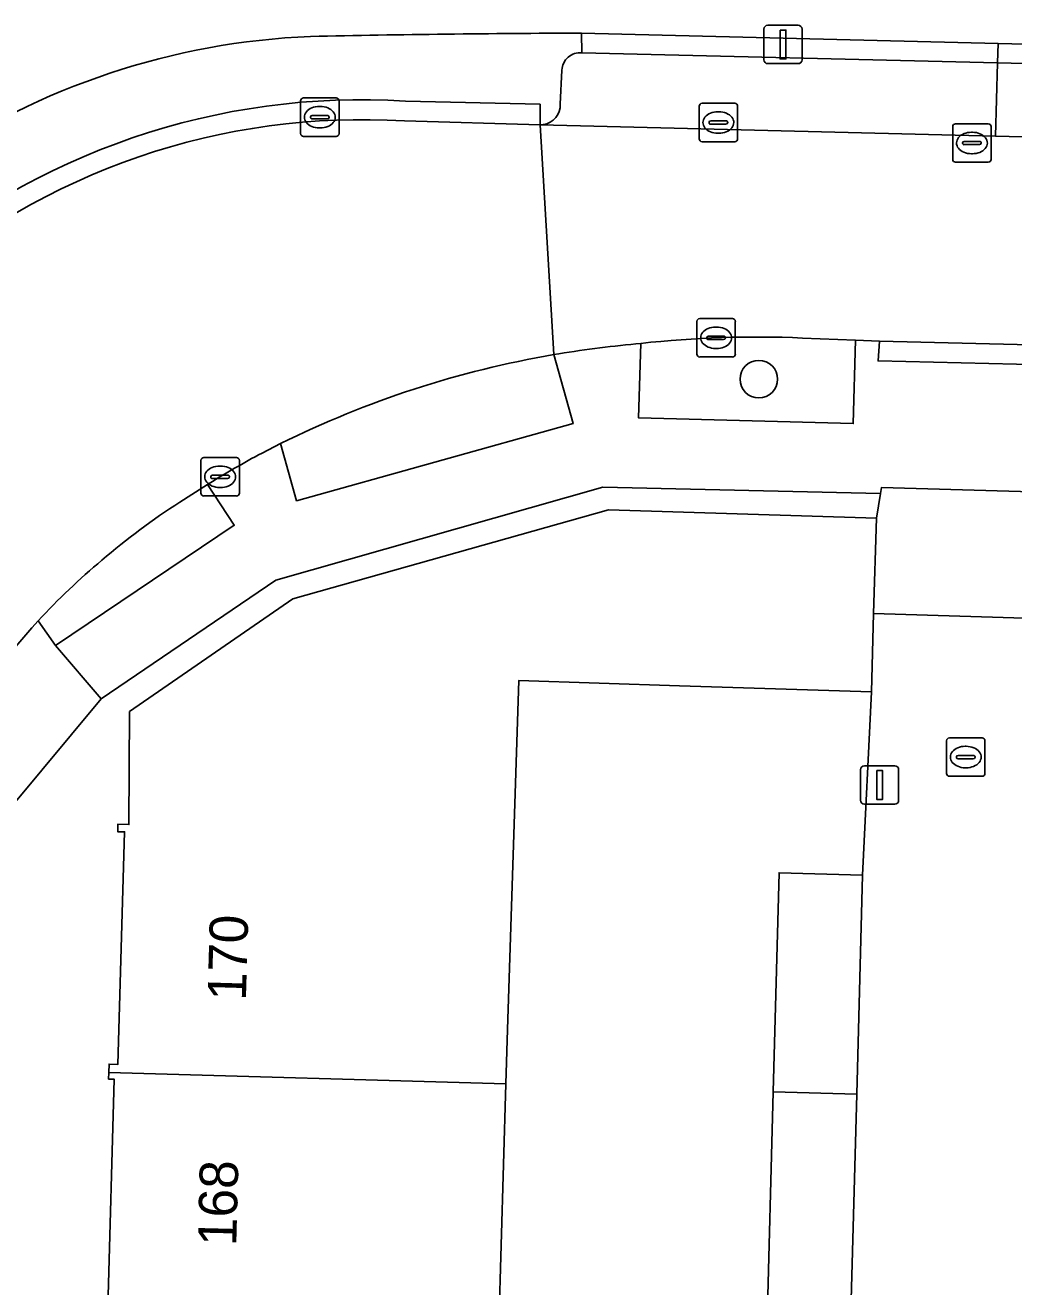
# Model space of a CAD drawing. Extents: x 162082 to 163401, y 388089 to 388636.
# Drawn here: x 162343.72 to 162369.45, y 388439.93 to 388472.76 of the extents above; entities that cross this region are included whole.
import ezdxf

# ---------------------------------------------------------------- set-up
doc = ezdxf.new("R2010")
doc.units = 0
for name, color, linetype in [('IMGEO_Berm_open', 7, 'Continuous'), ('IMGEO_Boom', 7, 'Continuous'), ('IMGEO_Erf', 7, 'Continuous'), ('IMGEO_Fietspad_gesloten', 7, 'Continuous'), ('IMGEO_Groenvoorziening', 7, 'Continuous'), ('IMGEO_Kolk', 7, 'Continuous'), ('IMGEO_Lichtmast', 7, 'Continuous'), ('IMGEO_Pand', 7, 'Continuous'), ('IMGEO_Pand_nummerreeks', 7, 'Continuous'), ('IMGEO_Parkeervlak_open', 7, 'Continuous'), ('IMGEO_Rijbaan_lokaal_gesloten', 7, 'Continuous'), ('IMGEO_Rijbaan_lokaal_open', 7, 'Continuous'), ('IMGEO_Rioolput', 7, 'Continuous'), ('IMGEO_Voetpad_open', 7, 'Continuous')]:
    doc.layers.add(name, color=color, linetype=linetype)

msp = doc.modelspace()

# ---------------------------------------------------------------- linework, layer by layer
at = {"layer": 'IMGEO_Berm_open'}
msp.add_lwpolyline([(162358.201, 388472.554), (162358.203, 388472.042), (162369.02, 388471.78), (162369.037, 388472.285)], close=True, dxfattribs=at)
at = {"layer": 'IMGEO_Boom'}
msp.add_circle((162362.811, 388463.549), 0.489, dxfattribs=at)
at = {"layer": 'IMGEO_Erf'}
for points in [[(162345.868, 388439.383), (162346.041, 388445.333), (162345.892, 388445.338), (162345.897, 388445.509), (162345.903, 388445.725), (162346.134, 388445.718), (162346.31, 388451.772), (162346.13, 388451.772), (162346.132, 388451.968), (162346.42, 388451.96), (162346.44, 388454.9), (162350.69, 388457.83), (162358.9, 388460.15), (162365.87, 388459.93), (162365.975, 388460.578), (162358.756, 388460.74), (162350.246, 388458.32), (162345.699, 388455.235), (162343.386, 388452.443), (162341.671, 388388.741)], [(162362.018, 388400.921), (162362.185, 388407.22), (162362.352, 388413.517), (162362.449, 388417.176), (162362.519, 388419.817), (162362.686, 388426.113), (162362.853, 388432.41), (162363.02, 388438.709), (162363.187, 388445.007), (162363.338, 388450.704), (162365.51, 388450.646), (162365.74, 388455.41), (162360.743, 388455.573), (162356.57, 388455.71), (162356.269, 388446.627), (162356.228, 388445.209), (162356.044, 388438.912), (162355.86, 388432.614), (162355.677, 388426.317), (162355.493, 388420.021), (162355.31, 388413.722), (162355.126, 388407.425), (162354.942, 388401.127), (162354.759, 388394.83)]]:
    msp.add_lwpolyline(points, dxfattribs=at)
at = {"layer": 'IMGEO_Fietspad_gesloten'}
msp.add_lwpolyline([(162358.201, 388472.554), (162369.037, 388472.285), (162375.078, 388472.135), (162386.708, 388471.847), (162390.238, 388471.759), (162401.837, 388471.472), (162408.03, 388471.318), (162408.007, 388470.829), (162416.505, 388470.602), (162416.525, 388471.113), (162420.862, 388471.019), (162440.416, 388470.49), (162440.436, 388470.49), (162448.448, 388470.301), (162458.442, 388470.036), (162464.998, 388469.844), (162475.747, 388469.573), (162481.767, 388469.41), (162492.263, 388469.129), (162498.783, 388468.948), (162509.296, 388468.657)], dxfattribs=at)
for centre, radius, start, end in [((162351.969, 388453.321), 19.166, 92.4584, 124.2977), ((162359.637, 388055.756), 416.8, 90.19737, 91.16714)]:
    msp.add_arc(centre, radius, start, end, dxfattribs=at)
at = {"layer": 'IMGEO_Groenvoorziening'}
for points in [[(162359.741, 388464.48), (162359.684, 388462.54), (162365.27, 388462.394), (162365.328, 388464.563)], [(162365.328, 388464.563), (162363.947, 388464.619)], [(162350.369, 388461.874), (162350.783, 388460.383), (162357.982, 388462.393), (162357.479, 388464.187)], [(162349.16, 388459.748), (162348.465, 388460.809), (162347.745, 388460.351)], [(162344.06, 388457.261), (162344.51, 388456.617), (162349.16, 388459.748)]]:
    msp.add_lwpolyline(points, dxfattribs=at)
for centre, radius, start, end in [((162362.739, 388437.47), 27.176, 87.4521, 96.3336), ((162361.826, 388438.741), 25.814, 99.6938, 116.3473), ((162357.594, 388445.058), 18.19, 122.7813, 130.75), ((162357.048, 388445.251), 17.69, 129.8206, 137.2418)]:
    msp.add_arc(centre, radius, start, end, dxfattribs=at)
at = {"layer": 'IMGEO_Kolk'}
for p, q in [((162361.333, 388470.727), (162362.185, 388470.727)), ((162361.258, 388469.801), (162361.258, 388470.653)), ((162361.746, 388470.507), (162361.771, 388470.507)), ((162362.259, 388470.653), (162362.259, 388469.801)), ((162361.517, 388470.221), (162361.517, 388470.233)), ((162361.955, 388470.184), (162361.557, 388470.184)), ((162361.56, 388470.27), (162361.958, 388470.27)), ((162362.001, 388470.233), (162362.001, 388470.221)), ((162361.769, 388469.947), (162361.744, 388469.947)), ((162362.185, 388469.727), (162361.333, 388469.727)), ((162361.199, 388464.2), (162361.199, 388465.052)), ((162361.274, 388465.126), (162362.126, 388465.126)), ((162361.687, 388464.906), (162361.712, 388464.906)), ((162362.2, 388465.052), (162362.2, 388464.2)), ((162361.458, 388464.62), (162361.458, 388464.632)), ((162361.896, 388464.583), (162361.498, 388464.583)), ((162361.501, 388464.669), (162361.899, 388464.669)), ((162361.942, 388464.632), (162361.942, 388464.62)), ((162361.71, 388464.346), (162361.685, 388464.346)), ((162362.126, 388464.126), (162361.274, 388464.126)), ((162348.294, 388460.583), (162348.294, 388461.435)), ((162348.369, 388461.509), (162349.221, 388461.509)), ((162348.782, 388461.289), (162348.807, 388461.289)), ((162349.295, 388461.435), (162349.295, 388460.583)), ((162348.553, 388461.003), (162348.553, 388461.015)), ((162348.991, 388460.966), (162348.593, 388460.966)), ((162348.596, 388461.052), (162348.994, 388461.052)), ((162349.037, 388461.015), (162349.037, 388461.003)), ((162348.805, 388460.729), (162348.78, 388460.729)), ((162349.221, 388460.509), (162348.369, 388460.509)), ((162367.695, 388453.29), (162367.695, 388454.142)), ((162367.77, 388454.216), (162368.622, 388454.216)), ((162368.183, 388453.996), (162368.208, 388453.996)), ((162368.696, 388454.142), (162368.696, 388453.29)), ((162367.954, 388453.71), (162367.954, 388453.722)), ((162368.392, 388453.673), (162367.994, 388453.673)), ((162367.997, 388453.759), (162368.395, 388453.759)), ((162368.438, 388453.722), (162368.438, 388453.71)), ((162368.206, 388453.436), (162368.181, 388453.436)), ((162368.622, 388453.216), (162367.77, 388453.216))]:
    msp.add_line(p, q, dxfattribs=at)
for points in [[(162361.333, 388470.727), (162362.185, 388470.727)], [(162361.258, 388469.801), (162361.258, 388470.653)], [(162362.259, 388470.653), (162362.259, 388469.801)], [(162362.185, 388469.727), (162361.333, 388469.727)], [(162361.199, 388464.2), (162361.199, 388465.052)], [(162361.274, 388465.126), (162362.126, 388465.126)], [(162362.2, 388465.052), (162362.2, 388464.2)], [(162362.126, 388464.126), (162361.274, 388464.126)], [(162348.294, 388460.583), (162348.294, 388461.435)], [(162348.369, 388461.509), (162349.221, 388461.509)], [(162349.295, 388461.435), (162349.295, 388460.583)], [(162349.221, 388460.509), (162348.369, 388460.509)], [(162367.695, 388453.29), (162367.695, 388454.142)], [(162367.77, 388454.216), (162368.622, 388454.216)], [(162368.696, 388454.142), (162368.696, 388453.29)], [(162368.622, 388453.216), (162367.77, 388453.216)]]:
    msp.add_lwpolyline(points, dxfattribs=at)
for centre, radius, start, end in [((162361.335, 388470.651), 0.0765, 91.552, 178.448), ((162361.335, 388470.651), 0.0765, 91.552, 178.448), ((162362.183, 388470.651), 0.0765, 1.552, 88.448), ((162362.183, 388470.651), 0.0765, 1.552, 88.448), ((162361.557, 388470.23), 0.0403, 85.8775, 175.7526), ((162361.554, 388470.22), 0.0366, 178.938, 274.7102), ((162361.958, 388470.227), 0.043, 264.8664, 352.4533), ((162361.962, 388470.232), 0.0386, 1.7309, 96.639), ((162361.335, 388469.803), 0.0765, 181.552, 268.448), ((162361.335, 388469.803), 0.0765, 181.552, 268.448), ((162362.183, 388469.803), 0.0765, 271.552, 358.448), ((162362.183, 388469.803), 0.0765, 271.552, 358.448), ((162361.276, 388465.05), 0.0765, 91.552, 178.448), ((162361.276, 388465.05), 0.0765, 91.552, 178.448), ((162362.124, 388465.05), 0.0765, 1.552, 88.448), ((162362.124, 388465.05), 0.0765, 1.552, 88.448), ((162361.498, 388464.629), 0.0403, 85.8775, 175.7526), ((162361.495, 388464.619), 0.0366, 178.938, 274.7102), ((162361.899, 388464.626), 0.043, 264.8664, 352.4533), ((162361.903, 388464.631), 0.0386, 1.7309, 96.639), ((162361.276, 388464.202), 0.0765, 181.552, 268.448), ((162361.276, 388464.202), 0.0765, 181.552, 268.448), ((162362.124, 388464.202), 0.0765, 271.552, 358.448), ((162362.124, 388464.202), 0.0765, 271.552, 358.448), ((162348.371, 388461.433), 0.0765, 91.552, 178.448), ((162348.371, 388461.433), 0.0765, 91.552, 178.448), ((162349.219, 388461.433), 0.0765, 1.552, 88.448), ((162349.219, 388461.433), 0.0765, 1.552, 88.448), ((162348.593, 388461.012), 0.0403, 85.8775, 175.7526), ((162348.59, 388461.002), 0.0366, 178.938, 274.7102), ((162348.994, 388461.009), 0.043, 264.8664, 352.4533), ((162348.998, 388461.014), 0.0386, 1.7309, 96.639), ((162348.371, 388460.585), 0.0765, 181.552, 268.448), ((162348.371, 388460.585), 0.0765, 181.552, 268.448), ((162349.219, 388460.585), 0.0765, 271.552, 358.448), ((162349.219, 388460.585), 0.0765, 271.552, 358.448), ((162367.772, 388454.14), 0.0765, 91.552, 178.448), ((162367.772, 388454.14), 0.0765, 91.552, 178.448), ((162368.62, 388454.14), 0.0765, 1.552, 88.448), ((162368.62, 388454.14), 0.0765, 1.552, 88.448), ((162367.994, 388453.719), 0.0403, 85.8775, 175.7526), ((162367.991, 388453.709), 0.0366, 178.938, 274.7102), ((162368.395, 388453.716), 0.043, 264.8664, 352.4533), ((162368.399, 388453.721), 0.0386, 1.7309, 96.639), ((162367.772, 388453.292), 0.0765, 181.552, 268.448), ((162367.772, 388453.292), 0.0765, 181.552, 268.448), ((162368.62, 388453.292), 0.0765, 271.552, 358.448), ((162368.62, 388453.292), 0.0765, 271.552, 358.448)]:
    msp.add_arc(centre, radius, start, end, dxfattribs=at)
for centre, major_axis, ratio, start_param, end_param in [((162361.745, 388470.227), (-0.387, 0.002), 0.722429, 4.712389, 7.853982), ((162361.77, 388470.227), (-0.39, 0.002), 0.717154, 1.570796, 4.712389), ((162361.686, 388464.626), (-0.387, 0.002), 0.722429, 4.712389, 7.853982), ((162361.711, 388464.626), (-0.39, 0.002), 0.717154, 1.570796, 4.712389), ((162348.781, 388461.009), (-0.387, 0.002), 0.722429, 4.712389, 7.853982), ((162348.806, 388461.009), (-0.39, 0.002), 0.717154, 1.570796, 4.712389), ((162368.182, 388453.716), (-0.387, 0.002), 0.722429, 4.712389, 7.853982), ((162368.207, 388453.716), (-0.39, 0.002), 0.717154, 1.570796, 4.712389)]:
    msp.add_ellipse(centre, major_axis=major_axis, ratio=ratio, start_param=start_param, end_param=end_param, dxfattribs=at)
at = {"layer": 'IMGEO_Lichtmast'}
for p, q in [((162363.045, 388472.759), (162363.835, 388472.759)), ((162363.835, 388472.759), (162363.045, 388472.759)), ((162362.945, 388471.859), (162362.945, 388472.659)), ((162362.945, 388472.659), (162362.945, 388471.859)), ((162363.935, 388472.659), (162363.935, 388471.859)), ((162363.935, 388471.859), (162363.935, 388472.659)), ((162363.835, 388471.759), (162363.045, 388471.759)), ((162363.045, 388471.759), (162363.835, 388471.759)), ((162365.46, 388452.59), (162365.46, 388453.39)), ((162365.46, 388453.39), (162365.46, 388452.59)), ((162365.56, 388453.49), (162366.35, 388453.49)), ((162366.35, 388453.49), (162365.56, 388453.49)), ((162366.45, 388453.39), (162366.45, 388452.59)), ((162366.45, 388452.59), (162366.45, 388453.39)), ((162366.35, 388452.49), (162365.56, 388452.49)), ((162365.56, 388452.49), (162366.35, 388452.49))]:
    msp.add_line(p, q, dxfattribs=at)
for points in [[(162363.365, 388472.634), (162363.515, 388472.634), (162363.515, 388471.884), (162363.365, 388471.884), (162363.365, 388472.634)], [(162365.88, 388453.365), (162366.03, 388453.365), (162366.03, 388452.615), (162365.88, 388452.615), (162365.88, 388453.365)]]:
    msp.add_lwpolyline(points, dxfattribs=at)
for centre, start, end in [((162363.045, 388472.659), 90, 180), ((162363.045, 388472.659), 90, 180), ((162363.835, 388472.659), 0, 90), ((162363.835, 388472.659), 360, 90), ((162363.045, 388471.859), 180, 270), ((162363.045, 388471.859), 180, 270), ((162363.835, 388471.859), 270, 0), ((162363.835, 388471.859), 270, 0), ((162365.56, 388453.39), 90, 180), ((162365.56, 388453.39), 90, 180), ((162366.35, 388453.39), 0, 90), ((162366.35, 388453.39), 360, 90), ((162365.56, 388452.59), 180, 270), ((162365.56, 388452.59), 180, 270), ((162366.35, 388452.59), 270, 0), ((162366.35, 388452.59), 270, 0)]:
    msp.add_arc(centre, 0.1, start, end, dxfattribs=at)
at = {"layer": 'IMGEO_Pand'}
for points in [[(162345.897, 388445.509), (162356.228, 388445.209), (162356.269, 388446.627), (162356.57, 388455.71), (162360.743, 388455.573), (162365.74, 388455.41), (162365.799, 388457.454), (162365.87, 388459.93), (162358.9, 388460.15), (162350.69, 388457.83), (162346.44, 388454.9), (162346.42, 388451.96), (162346.132, 388451.968), (162346.13, 388451.772), (162346.31, 388451.772), (162346.134, 388445.718), (162345.903, 388445.725)], [(162365.51, 388450.646), (162363.338, 388450.704), (162363.187, 388445.007), (162365.359, 388444.944)], [(162345.897, 388445.509), (162345.892, 388445.338), (162346.041, 388445.333), (162345.868, 388439.383), (162345.726, 388439.387), (162345.721, 388439.212), (162356.044, 388438.912), (162356.228, 388445.209)], [(162363.02, 388438.709), (162365.192, 388438.646), (162365.359, 388444.944), (162363.187, 388445.007)]]:
    msp.add_lwpolyline(points, close=True, dxfattribs=at)
at = {"layer": 'IMGEO_Parkeervlak_open'}
for points in [[(162369.02, 388471.78), (162358.203, 388472.042)], [(162357.2, 388470.174), (162357.12, 388470.167), (162368.972, 388469.873), (162369.02, 388471.78)], [(162357.689, 388471.589), (162357.643, 388470.708)]]:
    msp.add_lwpolyline(points, dxfattribs=at)
for centre, radius, start, end in [((162358.159, 388471.574), 0.47, 84.6243, 178.1566), ((162357.134, 388470.68), 0.51, 277.466, 3.1766)]:
    msp.add_arc(centre, radius, start, end, dxfattribs=at)
at = {"layer": 'IMGEO_Rijbaan_lokaal_gesloten'}
for points in [[(162357.479, 388464.187), (162357.12, 388470.167), (162353.588, 388470.267)], [(162504.674, 388466.396), (162498.717, 388466.552), (162492.196, 388466.723), (162481.721, 388466.997), (162474.776, 388467.179), (162471.449, 388467.262), (162471.402, 388467.266), (162464.938, 388467.441), (162458.384, 388467.618), (162448.429, 388467.886), (162439.373, 388468.131), (162439.33, 388468.131), (162438.401, 388468.167), (162419.774, 388468.618), (162418.749, 388468.644), (162408.223, 388468.89), (162403.702, 388469.023), (162402.728, 388469.034), (162390.18, 388469.346), (162386.66, 388469.431), (162375.01, 388469.723), (162368.972, 388469.873), (162357.12, 388470.167), (162357.479, 388464.187)], [(162359.611, 388464.465), (162359.741, 388464.48)], [(162363.947, 388464.619), (162365.328, 388464.563), (162365.948, 388464.538), (162370.967, 388464.412), (162371.659, 388464.386), (162390.127, 388463.916), (162391.354, 388463.895), (162408.184, 388463.445), (162420.621, 388463.13), (162421.807, 388463.11), (162462.126, 388462.081), (162463.206, 388462.062), (162475.436, 388461.725), (162497.037, 388461.139)], [(162349.884, 388461.627), (162350.369, 388461.874)], [(162347.745, 388460.351), (162348.465, 388460.809)]]:
    msp.add_lwpolyline(points, dxfattribs=at)
for centre, radius, start, end in [((162352.479, 388452.437), 17.865, 86.4419, 131.4689), ((162362.739, 388437.47), 27.176, 87.4521, 96.3336), ((162361.826, 388438.741), 25.814, 99.6938, 116.3473), ((162362.141, 388436.748), 27.832, 95.2155, 99.6428), ((162363.427, 388436.495), 28.549, 118.318, 121.6056), ((162357.594, 388445.058), 18.19, 122.7813, 130.75), ((162357.048, 388445.251), 17.69, 129.8206, 137.2418), ((162356.489, 388445.794), 16.911, 137.3069, 163.4762)]:
    msp.add_arc(centre, radius, start, end, dxfattribs=at)
at = {"layer": 'IMGEO_Rijbaan_lokaal_open'}
msp.add_lwpolyline([(162370.644, 388460.18), (162370.536, 388460.18), (162370.521, 388460.602), (162366.001, 388460.726), (162365.975, 388460.578), (162365.87, 388459.93), (162365.799, 388457.454), (162370.574, 388457.3)], close=True, dxfattribs=at)
msp.add_lwpolyline([(162370.574, 388457.3), (162365.799, 388457.454), (162365.74, 388455.41), (162365.51, 388450.646), (162365.359, 388444.944), (162365.192, 388438.646), (162365.025, 388432.347), (162364.858, 388426.05), (162364.754, 388422.116), (162366.299, 388422.059), (162369.325, 388421.97), (162372.351, 388421.882)], dxfattribs=at)
at = {"layer": 'IMGEO_Rioolput'}
for p, q in [((162350.888, 388469.939), (162350.888, 388470.791)), ((162350.963, 388470.865), (162351.815, 388470.865)), ((162351.889, 388470.791), (162351.889, 388469.939)), ((162351.19, 388470.408), (162351.588, 388470.408)), ((162351.376, 388470.645), (162351.401, 388470.645)), ((162351.147, 388470.359), (162351.147, 388470.371)), ((162351.585, 388470.322), (162351.187, 388470.322)), ((162351.399, 388470.085), (162351.374, 388470.085)), ((162351.631, 388470.371), (162351.631, 388470.359)), ((162367.856, 388469.268), (162367.856, 388470.12)), ((162367.931, 388470.194), (162368.783, 388470.194)), ((162368.857, 388470.12), (162368.857, 388469.268)), ((162351.815, 388469.865), (162350.963, 388469.865)), ((162368.158, 388469.737), (162368.556, 388469.737)), ((162368.344, 388469.974), (162368.369, 388469.974)), ((162368.115, 388469.688), (162368.115, 388469.7)), ((162368.553, 388469.651), (162368.155, 388469.651)), ((162368.367, 388469.414), (162368.342, 388469.414)), ((162368.599, 388469.7), (162368.599, 388469.688)), ((162368.783, 388469.194), (162367.931, 388469.194))]:
    msp.add_line(p, q, dxfattribs=at)
for points in [[(162350.888, 388469.939), (162350.888, 388470.791)], [(162350.963, 388470.865), (162351.815, 388470.865)], [(162351.889, 388470.791), (162351.889, 388469.939)], [(162367.856, 388469.268), (162367.856, 388470.12)], [(162367.931, 388470.194), (162368.783, 388470.194)], [(162368.857, 388470.12), (162368.857, 388469.268)], [(162351.815, 388469.865), (162350.963, 388469.865)], [(162368.783, 388469.194), (162367.931, 388469.194)]]:
    msp.add_lwpolyline(points, dxfattribs=at)
for centre, radius, start, end in [((162350.965, 388470.789), 0.0765, 91.552, 178.448), ((162350.965, 388470.789), 0.0765, 91.552, 178.448), ((162351.813, 388470.789), 0.0765, 1.552, 88.448), ((162351.813, 388470.789), 0.0765, 1.552, 88.448), ((162351.187, 388470.368), 0.0403, 85.8775, 175.7526), ((162351.592, 388470.37), 0.0386, 1.7309, 96.639), ((162351.184, 388470.358), 0.0366, 178.938, 274.7102), ((162351.588, 388470.365), 0.043, 264.8664, 352.4533), ((162367.933, 388470.118), 0.0765, 91.552, 178.448), ((162367.933, 388470.118), 0.0765, 91.552, 178.448), ((162368.781, 388470.118), 0.0765, 1.552, 88.448), ((162368.781, 388470.118), 0.0765, 1.552, 88.448), ((162350.965, 388469.941), 0.0765, 181.552, 268.448), ((162350.965, 388469.941), 0.0765, 181.552, 268.448), ((162351.813, 388469.941), 0.0765, 271.552, 358.448), ((162351.813, 388469.941), 0.0765, 271.552, 358.448), ((162368.155, 388469.697), 0.0403, 85.8775, 175.7526), ((162368.56, 388469.699), 0.0386, 1.7309, 96.639), ((162368.152, 388469.687), 0.0366, 178.938, 274.7102), ((162368.556, 388469.694), 0.043, 264.8664, 352.4533), ((162367.933, 388469.27), 0.0765, 181.552, 268.448), ((162367.933, 388469.27), 0.0765, 181.552, 268.448), ((162368.781, 388469.27), 0.0765, 271.552, 358.448), ((162368.781, 388469.27), 0.0765, 271.552, 358.448)]:
    msp.add_arc(centre, radius, start, end, dxfattribs=at)
for centre, major_axis, ratio, start_param, end_param in [((162351.375, 388470.365), (-0.387, 0.002), 0.722429, 4.712389, 7.853982), ((162351.4, 388470.365), (-0.39, 0.002), 0.717154, 1.570796, 4.712389), ((162368.343, 388469.694), (-0.387, 0.002), 0.722429, 4.712389, 7.853982), ((162368.368, 388469.694), (-0.39, 0.002), 0.717154, 1.570796, 4.712389)]:
    msp.add_ellipse(centre, major_axis=major_axis, ratio=ratio, start_param=start_param, end_param=end_param, dxfattribs=at)
at = {"layer": 'IMGEO_Voetpad_open'}
for points in [[(162358.203, 388472.042), (162358.201, 388472.554)], [(162357.643, 388470.708), (162357.689, 388471.589)], [(162353.588, 388470.267), (162357.12, 388470.167), (162357.12, 388470.702), (162353.614, 388470.786)], [(162353.614, 388470.786), (162357.12, 388470.702), (162357.12, 388470.167)], [(162357.12, 388470.167), (162357.2, 388470.174)], [(162371.659, 388464.386), (162370.967, 388464.412), (162370.954, 388463.902), (162365.916, 388464.025), (162365.948, 388464.538), (162365.328, 388464.563), (162365.27, 388462.394), (162359.684, 388462.54), (162359.741, 388464.48), (162359.611, 388464.465)], [(162357.479, 388464.187), (162357.982, 388462.393), (162350.783, 388460.383), (162350.369, 388461.874), (162349.884, 388461.627)], [(162348.465, 388460.809), (162349.16, 388459.748), (162344.51, 388456.617), (162345.699, 388455.235), (162350.246, 388458.32), (162358.756, 388460.74), (162365.975, 388460.578), (162366.001, 388460.726), (162370.521, 388460.602), (162370.546, 388460.711), (162370.655, 388460.714), (162370.734, 388460.717), (162370.734, 388460.784), (162383.691, 388460.456), (162433.966, 388459.183), (162434.894, 388459.159), (162435.462, 388459.144), (162475.598, 388458.096), (162498.856, 388457.469), (162500.341, 388457.43), (162525.566, 388456.776)], [(162343.386, 388452.443), (162345.699, 388455.235), (162344.51, 388456.617), (162344.06, 388457.261)]]:
    msp.add_lwpolyline(points, dxfattribs=at)
for points in [[(162375.078, 388472.135), (162369.037, 388472.285), (162369.02, 388471.78), (162375.054, 388471.636)], [(162375.054, 388471.636), (162369.02, 388471.78), (162368.972, 388469.873), (162375.01, 388469.723)], [(162370.967, 388464.412), (162365.948, 388464.538), (162365.916, 388464.025), (162370.954, 388463.902)]]:
    msp.add_lwpolyline(points, close=True, dxfattribs=at)
for centre, radius, start, end in [((162351.969, 388453.321), 19.166, 92.4584, 124.2977), ((162359.637, 388055.756), 416.8, 90.19737, 91.16714), ((162358.159, 388471.574), 0.47, 84.6243, 178.1566), ((162352.481, 388452.393), 18.428, 86.4754, 131.3477), ((162352.481, 388452.393), 18.428, 86.4754, 131.3477), ((162357.134, 388470.68), 0.51, 277.466, 3.1766), ((162352.479, 388452.437), 17.865, 86.4419, 131.4689), ((162362.141, 388436.748), 27.832, 95.2155, 99.6428), ((162363.427, 388436.495), 28.549, 118.318, 121.6056), ((162356.489, 388445.794), 16.911, 137.3069, 163.4762)]:
    msp.add_arc(centre, radius, start, end, dxfattribs=at)

# ---------------------------------------------------------------- texts
at = {"layer": 'IMGEO_Pand_nummerreeks'}
for s, rotation, p in [('170', 88.3348, (162349.464, 388447.367)), ('168', 88.5712, (162349.214, 388440.982))]:
    msp.add_text(s, height=1, rotation=rotation, dxfattribs=at).set_placement(p)

doc.saveas('drawing.dxf')
